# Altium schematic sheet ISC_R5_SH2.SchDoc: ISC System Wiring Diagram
size B; DrawnBy: Filiberto Clara; Engineer: Filiberto Clara; Organization: LIGO Laboratory; Address1: California Institute of Technology; Address2: Massachusetts Institute of Technology; SheetNumber: 20; SheetTotal: 37
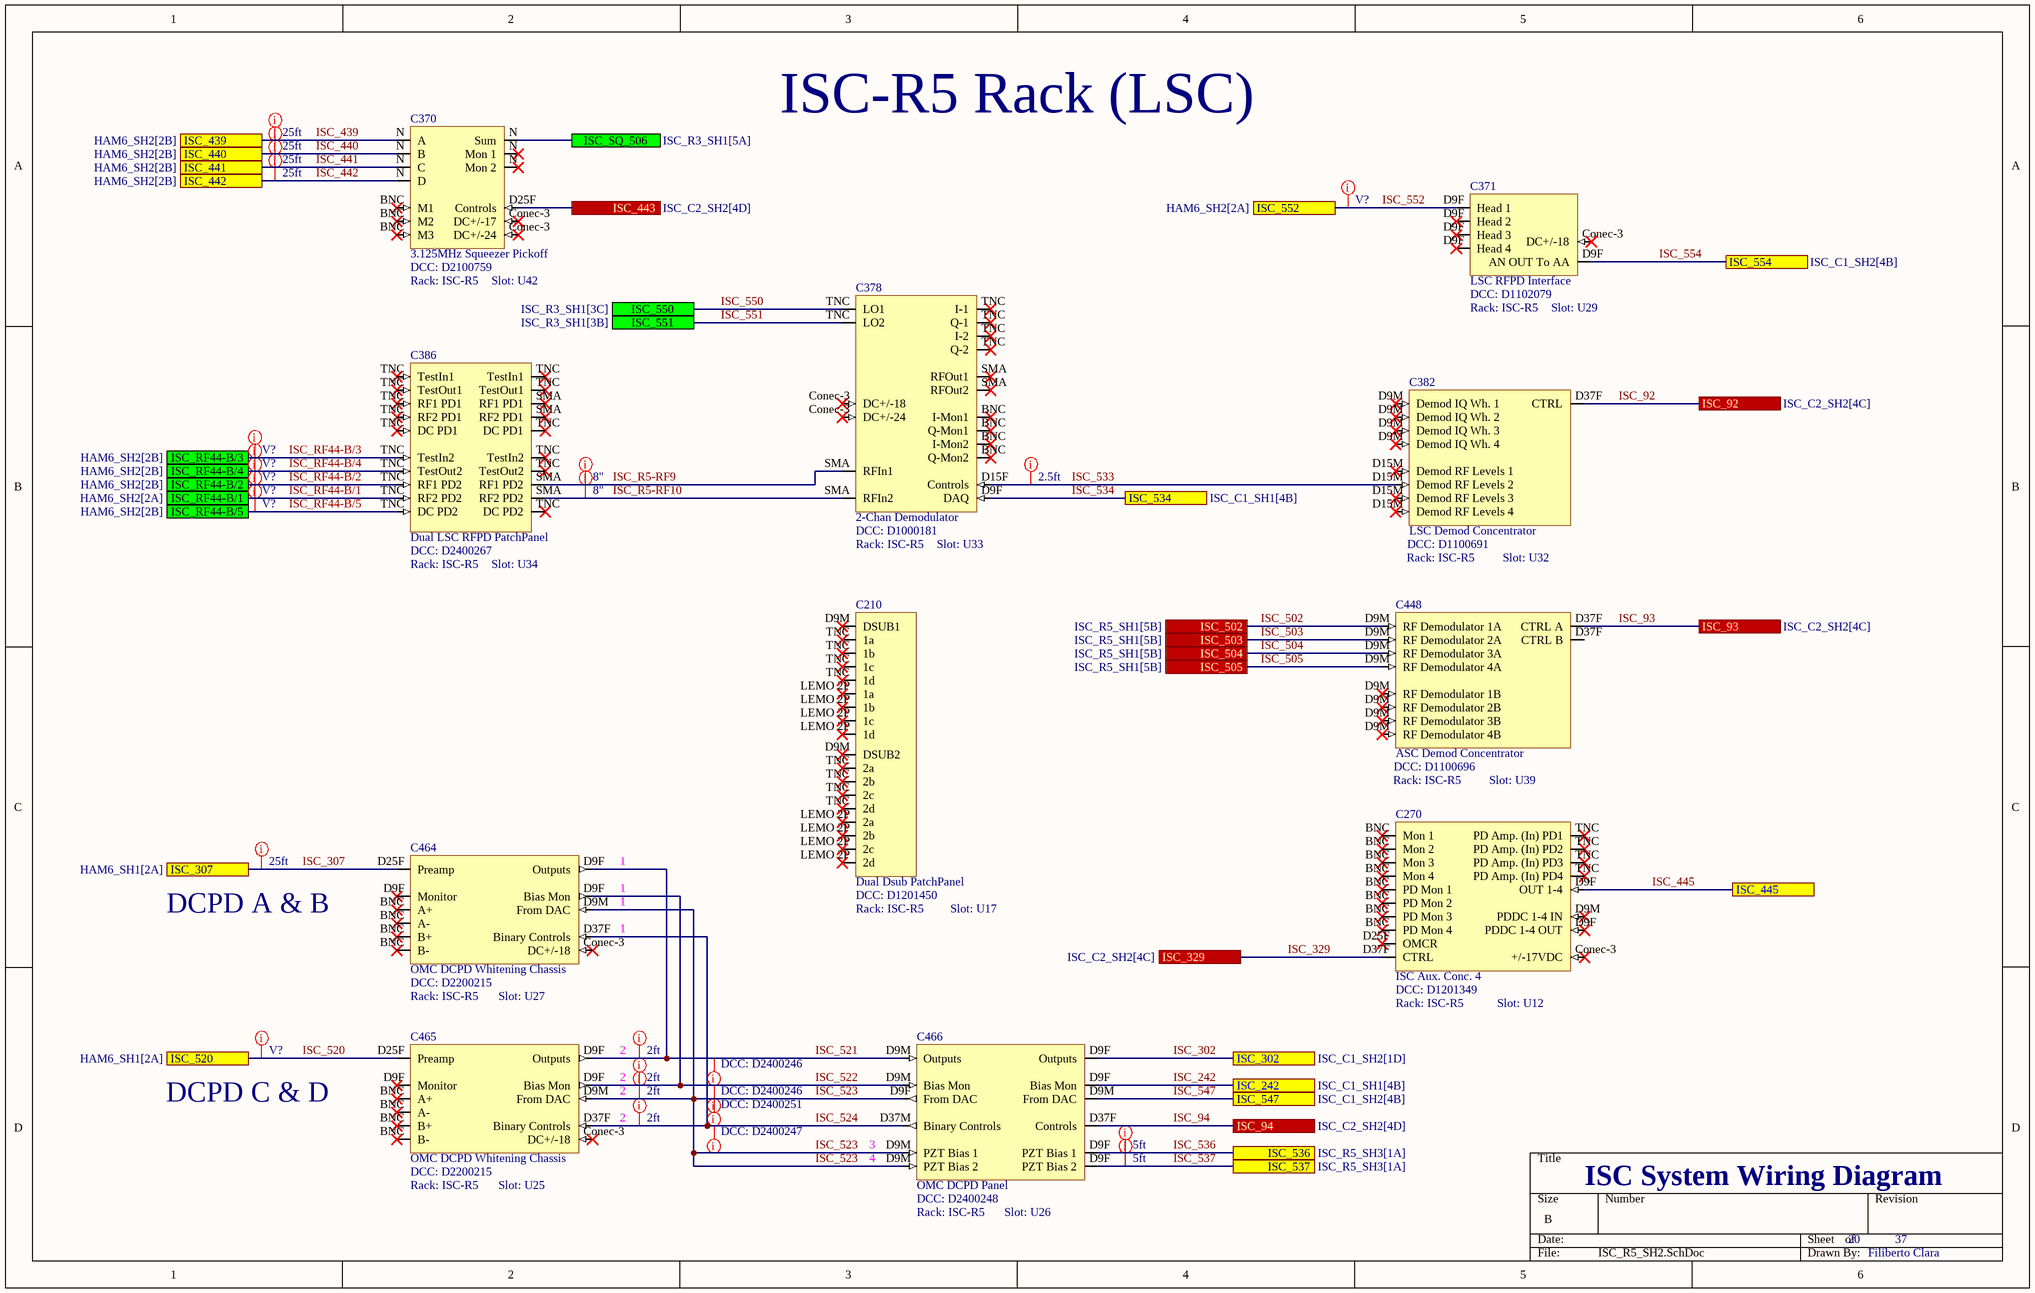
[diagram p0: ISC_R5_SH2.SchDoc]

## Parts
C210  Dual Dsub PatchPanel  DCC: D1201450  Rack: ISC-R5  Slot: U17
C270  ISC Aux. Conc. 4  DCC: D1201349  Rack: ISC-R5  Slot: U12
C370  3.125MHz Squeezer Pickoff  DCC: D2100759  Rack: ISC-R5  Slot: U42
C371  LSC RFPD Interface  DCC: D1102079  Rack: ISC-R5  Slot: U29
C378  2-Chan Demodulator  DCC: D1000181  Rack: ISC-R5  Slot: U33
C382  LSC Demod Concentrator  DCC: D1100691  Rack: ISC-R5  Slot: U32
C386  Dual LSC RFPD PatchPanel  DCC: D2400267  Rack: ISC-R5  Slot: U34
C448  ASC Demod Concentrator  DCC: D1100696  Rack: ISC-R5  Slot: U39
C464  OMC DCPD Whitening Chassis  DCC: D2200215  Rack: ISC-R5  Slot: U27
C465  OMC DCPD Whitening Chassis  DCC: D2200215  Rack: ISC-R5  Slot: U25
C466  OMC DCPD Panel  DCC: D2400248  Rack: ISC-R5  Slot: U26

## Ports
ISC_92 (see ISC_C2_SH2[4C]), ISC_93 (see ISC_C2_SH2[4C]), ISC_94 (see ISC_C2_SH2[4D]), ISC_242 (see ISC_C1_SH1[4B]), ISC_302 (see ISC_C1_SH2[1D]), ISC_307 (see HAM6_SH1[2A]), ISC_329 (see ISC_C2_SH2[4C]), ISC_439 (see HAM6_SH2[2B]), ISC_440 (see HAM6_SH2[2B]), ISC_441 (see HAM6_SH2[2B]), ISC_442 (see HAM6_SH2[2B]), ISC_443 (see ISC_C2_SH2[4D]), ISC_445, ISC_502 (see ISC_R5_SH1[5B]), ISC_503 (see ISC_R5_SH1[5B]), ISC_504 (see ISC_R5_SH1[5B]), ISC_505 (see ISC_R5_SH1[5B]), ISC_520 (see HAM6_SH1[2A]), ISC_534 (see ISC_C1_SH1[4B]), ISC_536 (see ISC_R5_SH3[1A]), ISC_537 (see ISC_R5_SH3[1A]), ISC_547 (see ISC_C1_SH2[4B]), ISC_550 (see ISC_R3_SH1[3C]), ISC_551 (see ISC_R3_SH1[3B]), ISC_552 (see HAM6_SH2[2A]), ISC_554 (see ISC_C1_SH2[4B]), ISC_RF44-B/1 (see HAM6_SH2[2A]), ISC_RF44-B/2 (see HAM6_SH2[2B]), ISC_RF44-B/3 (see HAM6_SH2[2B]), ISC_RF44-B/4 (see HAM6_SH2[2B]), ISC_RF44-B/5 (see HAM6_SH2[2B]), ISC_SQ_506 (see ISC_R3_SH1[5A])

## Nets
ISC_92: C382.D37F(CTRL) ; port ISC_92
ISC_93: C448.D37F(CTRL_A) ; port ISC_93
ISC_94: C466.D37F(Controls) ; port ISC_94
ISC_242: C466.D9F(Bias_Mon) ; port ISC_242
ISC_302: C466.D9F(Outputs) ; port ISC_302
ISC_307: C464.D25F(Preamp) ; port ISC_307
ISC_329: C270.D37F(CTRL) ; port ISC_329
ISC_439: C370.N(A) ; port ISC_439
ISC_440: C370.N(B) ; port ISC_440
ISC_441: C370.N(C) ; port ISC_441
ISC_442: C370.N(D) ; port ISC_442
ISC_443: C370.D25F(Controls) ; port ISC_443
ISC_445: C270.D9F(PDDC_1-4_OUT) ; port ISC_445
ISC_502: C448.D9M(RF_Demodulator_1A) ; port ISC_502
ISC_503: C448.D9M(RF_Demodulator_2A) ; port ISC_503
ISC_504: C448.D9M(RF_Demodulator_3A) ; port ISC_504
ISC_505: C448.D9M(RF_Demodulator_4A) ; port ISC_505
ISC_520: C465.D25F(Preamp) ; port ISC_520
ISC_521: C464.D9F(Outputs) C465.D9F(Outputs) C466.D9M(Outputs)
ISC_522: C464.D9F(Bias_Mon) C465.D9F(Bias_Mon) C466.D9M(Bias_Mon)
ISC_523: C464.D9M(From_DAC) C465.D9M(From_DAC) C466.D9F(From_DAC) C466.D9M(PZT_Bias_1)
ISC_524: C464.D37F(Binary_Controls) C465.D37F(Binary_Controls) C466.D37M(Binary_Controls)
ISC_533: C378.D15F(Controls) C382.D15M(Demod_RF_Levels_1)
ISC_534: C378.D9F(DAQ) ; port ISC_534
ISC_536: C466.D9F(PZT_Bias_1) ; port ISC_536
ISC_537: C466.D9F(PZT_Bias_2) ; port ISC_537
ISC_547: C466.D9M(From_DAC) ; port ISC_547
ISC_550: C378.TNC(LO1) ; port ISC_550
ISC_551: C378.TNC(LO2) ; port ISC_551
ISC_552: C371.D9F(Head_1) ; port ISC_552
ISC_554: C371.D9F(AN_OUT_To_AA) ; port ISC_554
ISC_R5-RF9: C378.SMA(RFOut1) C386.SMA(RF1_PD1)
ISC_R5-RF10: C378.SMA(RFIn2) C386.SMA(RF2_PD2)
ISC_RF44-B/1: C386.TNC(RF2_PD2) ; port ISC_RF44-B/1
ISC_RF44-B/2: C386.TNC(RF1_PD2) ; port ISC_RF44-B/2
ISC_RF44-B/3: C386.TNC(TestIn1) ; port ISC_RF44-B/3
ISC_RF44-B/4: C386.TNC(TestOut2) ; port ISC_RF44-B/4
ISC_RF44-B/5: C386.TNC(DC_PD2) ; port ISC_RF44-B/5
ISC_SQ_506: C370.N(Sum) ; port ISC_SQ_506

Not connected (* = marked no-connect by the designer): C210 D9M(DSUB1)* LEMO 2P(1a)* TNC(1a)*; C270 BNC(PD_Mon_1)* Conec-3(+/-17VDC)* D9M(PDDC_1-4_IN)* D25F(OMCR)* TNC(PD_Amp._(In)_PD1)*; C370 BNC(M1)* Conec-3(DC+/-17)*; C371 Conec-3(DC+/-18)*; C378 BNC(I-Mon1)* Conec-3(DC+/-18)*; C382 D9M(Demod_IQ_Wh._1)*; C464 BNC(A+)* Conec-3(DC+/-18)*; C465 BNC(A+)* Conec-3(DC+/-18)*

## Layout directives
Length: 25ft: ISC_307, ISC_439, ISC_440, ISC_441, ISC_442
Length: 8": ISC_R5-RF9, ISC_R5-RF10
Length: 2.5ft: ISC_533
Length: V?: ISC_520, ISC_552, ISC_RF44-B/1, ISC_RF44-B/2, ISC_RF44-B/3, ISC_RF44-B/4, ISC_RF44-B/5
Length: 2ft: ISC_521, ISC_522, ISC_523, ISC_524
DCC: D2400247: ISC_524
DCC: D2400251: ISC_523
DCC: D2400246: ISC_521, ISC_522
Length: 5ft: ISC_536, ISC_537

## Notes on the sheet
- ISC-R5 Rack (LSC)
- DCPD A & B
- (near C464) 1
- DCPD C & D
- (near C465) 2
- (near C466) 3
- (near C466) 4

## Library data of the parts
C210 = Dual Dsub PatchPanel: Serial: Sxxxxxxx; System: ISC
C270 = ISC Aux. Conc. 4: Serial: Sxxxxxxx
C370 = 3.125MHz Squeezer Pickoff: Serial: Sxxxxxxx; System: ISC
C371 = LSC RFPD Interface: Serial: Sxxxxxxx; System: ISC
C378 = 2-Chan Demod: Serial: Sxxxxxxx; System: ISC
C382 = LSC Demod Concentrator: Serial: Sxxxxxxx; System: ISC
C386 = LSC RFPD PatchPanel Dual: Serial: Sxxxxxxx; System: ISC
C448 = ASC Demod Concentrator: Serial: Sxxxxxxx; System: ISC
C464 C465 = OMC DCPD Whitening Chassis: Serial: Sxxxxxxx; System: ISC
C466 = OMC DCPD Panel: Serial: Sxxxxxxx; System: ISC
